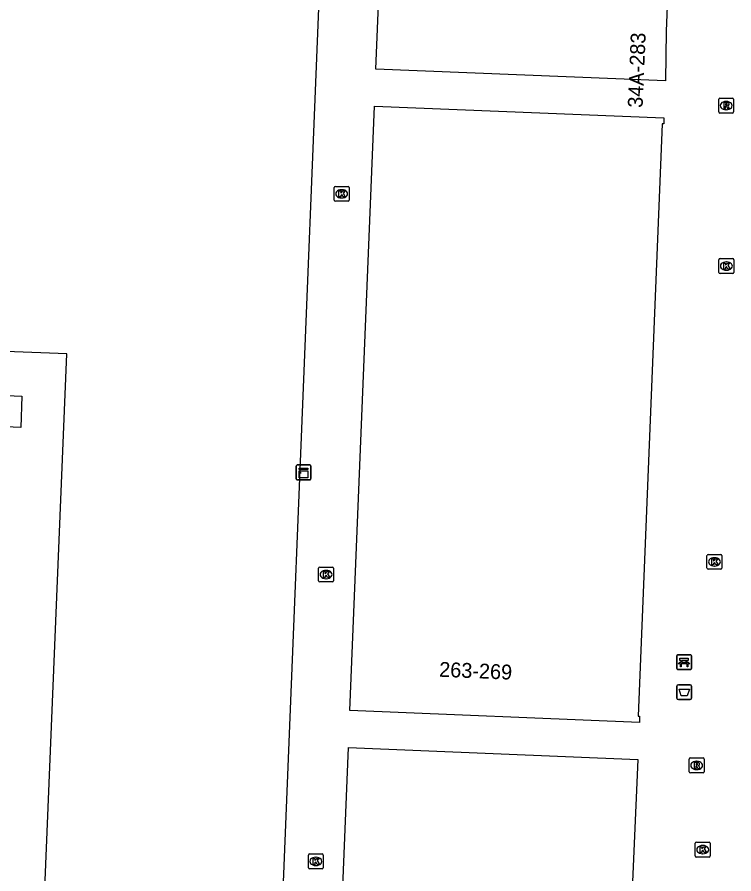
# Model space of a CAD drawing. Extents: x 160891 to 161384, y 386490 to 386907.
# Drawn here: x 161140.9 to 161189.1, y 386595.4 to 386653 of the extents above; entities that cross this region are included whole.
import ezdxf

# ---------------------------------------------------------------- set-up
doc = ezdxf.new("R2010")
doc.units = 0
for name, color, linetype in [('IMGEO_Afvalbak', 7, 'Continuous'), ('IMGEO_Bank', 7, 'Continuous'), ('IMGEO_Kast', 7, 'Continuous'), ('IMGEO_Kolk', 7, 'Continuous'), ('IMGEO_Pand', 7, 'Continuous'), ('IMGEO_Pand_nummerreeks', 7, 'Continuous'), ('IMGEO_Rioolput', 7, 'Continuous'), ('IMGEO_Voetgangersgebied_open', 7, 'Continuous')]:
    doc.layers.add(name, color=color, linetype=linetype)

msp = doc.modelspace()

# ---------------------------------------------------------------- linework, layer by layer
at = {"layer": 'IMGEO_Afvalbak'}
for p, q in [((161185.269, 386607.204), (161185.269, 386608.004)), ((161185.269, 386608.004), (161185.269, 386607.204)), ((161185.369, 386608.104), (161186.159, 386608.104)), ((161186.159, 386608.104), (161185.369, 386608.104)), ((161186.259, 386608.004), (161186.259, 386607.204)), ((161186.259, 386607.204), (161186.259, 386608.004)), ((161186.159, 386607.104), (161185.369, 386607.104)), ((161185.369, 386607.104), (161186.159, 386607.104))]:
    msp.add_line(p, q, dxfattribs=at)
msp.add_lwpolyline([(161185.412, 386607.818), (161186.116, 386607.818), (161185.967, 386607.348), (161185.561, 386607.348), (161185.412, 386607.818)], dxfattribs=at)
for centre, start, end in [((161185.369, 386608.004), 90, 180), ((161185.369, 386608.004), 90, 180), ((161186.159, 386608.004), 0, 90), ((161186.159, 386608.004), 360, 90), ((161185.369, 386607.204), 180, 270), ((161185.369, 386607.204), 180, 270), ((161186.159, 386607.204), 270, 0), ((161186.159, 386607.204), 270, 0)]:
    msp.add_arc(centre, 0.1, start, end, dxfattribs=at)
at = {"layer": 'IMGEO_Bank'}
for p, q in [((161185.256, 386609.198), (161185.256, 386610.039)), ((161185.256, 386610.039), (161185.256, 386609.198)), ((161185.331, 386610.123), (161186.172, 386610.123)), ((161186.172, 386610.123), (161185.331, 386610.123)), ((161186.256, 386610.048), (161186.256, 386609.207)), ((161186.256, 386609.207), (161186.256, 386610.048)), ((161185.953, 386609.521), (161185.56, 386609.521)), ((161185.565, 386609.629), (161185.565, 386609.735)), ((161185.609, 386609.735), (161185.609, 386609.629)), ((161185.897, 386609.741), (161185.615, 386609.741)), ((161185.615, 386609.623), (161185.897, 386609.623)), ((161185.903, 386609.629), (161185.903, 386609.735)), ((161185.947, 386609.735), (161185.947, 386609.629)), ((161186.181, 386609.123), (161185.34, 386609.123)), ((161185.34, 386609.123), (161186.181, 386609.123))]:
    msp.add_line(p, q, dxfattribs=at)
for points in [[(161185.503, 386609.521), (161185.361, 386609.521), (161185.473, 386609.623), (161185.559, 386609.623)], [(161185.559, 386609.741), (161185.473, 386609.741), (161185.473, 386609.902), (161186.036, 386609.902), (161186.036, 386609.741), (161185.953, 386609.741)], [(161185.553, 386609.514), (161185.553, 386609.307), (161185.51, 386609.307), (161185.51, 386609.514)], [(161185.953, 386609.623), (161186.036, 386609.623), (161186.148, 386609.521), (161186.009, 386609.521)], [(161186.003, 386609.514), (161186.003, 386609.307), (161185.959, 386609.307), (161185.959, 386609.514)]]:
    msp.add_lwpolyline(points, dxfattribs=at)
for centre, radius, start, end in [((161185.334, 386610.045), 0.0779, 92.4484, 184.28452), ((161185.334, 386610.045), 0.0779, 92.4484, 184.28452), ((161186.178, 386610.045), 0.0779, 2.4484, 94.28452), ((161186.178, 386610.045), 0.0779, 2.4484, 94.28452), ((161185.503, 386609.514), 0.00671, 2.89567, 87.10433), ((161185.56, 386609.514), 0.00671, 92.89567, 177.10433), ((161185.558, 386609.734), 0.00671, 2.89567, 87.10433), ((161185.558, 386609.63), 0.00671, 272.89567, 357.10433), ((161185.615, 386609.734), 0.00671, 92.89567, 177.10433), ((161185.615, 386609.63), 0.00671, 182.89567, 267.10433), ((161185.897, 386609.734), 0.00671, 2.89567, 87.10433), ((161185.897, 386609.63), 0.00671, 272.89567, 357.10433), ((161185.954, 386609.734), 0.00671, 92.89567, 177.10433), ((161185.954, 386609.63), 0.00671, 182.89567, 267.10433), ((161185.952, 386609.514), 0.00671, 2.89567, 87.10433), ((161186.009, 386609.514), 0.00671, 92.89567, 177.10433), ((161185.334, 386609.201), 0.0779, 182.4484, 274.28452), ((161185.334, 386609.201), 0.0779, 182.4484, 274.28452), ((161186.178, 386609.201), 0.0779, 272.4484, 4.28452), ((161186.178, 386609.201), 0.0779, 272.4484, 4.28452)]:
    msp.add_arc(centre, radius, start, end, dxfattribs=at)
at = {"layer": 'IMGEO_Kast'}
for p, q in [((161159.663, 386621.964), (161159.663, 386622.805)), ((161159.663, 386622.805), (161159.663, 386621.964)), ((161159.738, 386622.889), (161160.579, 386622.889)), ((161160.579, 386622.889), (161159.738, 386622.889)), ((161160.663, 386622.814), (161160.663, 386621.973)), ((161160.663, 386621.973), (161160.663, 386622.814)), ((161160.588, 386621.889), (161159.747, 386621.889)), ((161159.747, 386621.889), (161160.588, 386621.889))]:
    msp.add_line(p, q, dxfattribs=at)
for points in [[(161159.858, 386622.679), (161160.458, 386622.679), (161160.458, 386622.594), (161159.858, 386622.594), (161159.858, 386622.679)], [(161159.858, 386622.504), (161160.458, 386622.504), (161160.458, 386622.015), (161159.858, 386622.015), (161159.858, 386622.504)]]:
    msp.add_lwpolyline(points, dxfattribs=at)
msp.add_circle((161159.942, 386622.353), 0.0377, dxfattribs=at)
for centre, start, end in [((161159.741, 386622.811), 92.4484, 184.28452), ((161159.741, 386622.811), 92.4484, 184.28452), ((161160.585, 386622.811), 2.4484, 94.28452), ((161160.585, 386622.811), 2.4484, 94.28452), ((161159.741, 386621.967), 182.4484, 274.28452), ((161159.741, 386621.967), 182.4484, 274.28452), ((161160.585, 386621.967), 272.4484, 4.28452), ((161160.585, 386621.967), 272.4484, 4.28452)]:
    msp.add_arc(centre, 0.0779, start, end, dxfattribs=at)
at = {"layer": 'IMGEO_Kolk'}
for p, q in [((161162.226, 386640.703), (161162.226, 386641.555)), ((161162.301, 386641.629), (161163.153, 386641.629)), ((161162.714, 386641.409), (161162.739, 386641.409)), ((161163.227, 386641.555), (161163.227, 386640.703)), ((161163.153, 386640.629), (161162.301, 386640.629)), ((161162.737, 386640.849), (161162.712, 386640.849)), ((161188.098, 386635.846), (161188.098, 386636.698)), ((161188.173, 386636.772), (161189.025, 386636.772)), ((161188.586, 386636.552), (161188.611, 386636.552)), ((161189.099, 386636.698), (161189.099, 386635.846)), ((161188.609, 386635.992), (161188.584, 386635.992)), ((161189.025, 386635.772), (161188.173, 386635.772)), ((161187.293, 386615.945), (161187.293, 386616.797)), ((161187.368, 386616.871), (161188.22, 386616.871)), ((161187.781, 386616.651), (161187.806, 386616.651)), ((161188.294, 386616.797), (161188.294, 386615.945)), ((161161.177, 386615.094), (161161.177, 386615.946)), ((161161.252, 386616.02), (161162.104, 386616.02)), ((161161.665, 386615.8), (161161.69, 386615.8)), ((161162.178, 386615.946), (161162.178, 386615.094)), ((161188.22, 386615.871), (161187.368, 386615.871)), ((161187.804, 386616.091), (161187.779, 386616.091)), ((161161.688, 386615.24), (161161.663, 386615.24)), ((161162.104, 386615.02), (161161.252, 386615.02)), ((161186.506, 386596.586), (161186.506, 386597.438)), ((161186.581, 386597.512), (161187.433, 386597.512)), ((161187.507, 386597.438), (161187.507, 386596.586)), ((161186.994, 386597.292), (161187.019, 386597.292)), ((161160.489, 386595.797), (161160.489, 386596.649)), ((161160.564, 386596.723), (161161.416, 386596.723)), ((161160.977, 386596.503), (161161.002, 386596.503)), ((161161.49, 386596.649), (161161.49, 386595.797)), ((161187.433, 386596.512), (161186.581, 386596.512)), ((161187.017, 386596.732), (161186.992, 386596.732)), ((161161.416, 386595.723), (161160.564, 386595.723)), ((161161, 386595.943), (161160.975, 386595.943))]:
    msp.add_line(p, q, dxfattribs=at)
for points in [[(161162.226, 386640.703), (161162.226, 386641.555)], [(161162.301, 386641.629), (161163.153, 386641.629)], [(161162.547, 386641.329), (161162.67, 386641.329), (161162.67, 386641.178), (161162.8, 386641.329), (161162.964, 386641.329), (161162.818, 386641.178), (161162.971, 386640.929), (161162.819, 386640.929), (161162.734, 386641.093), (161162.67, 386641.026), (161162.67, 386640.929), (161162.547, 386640.929), (161162.547, 386641.329)], [(161163.227, 386641.555), (161163.227, 386640.703)], [(161163.153, 386640.629), (161162.301, 386640.629)], [(161188.098, 386635.846), (161188.098, 386636.698)], [(161188.173, 386636.772), (161189.025, 386636.772)], [(161189.099, 386636.698), (161189.099, 386635.846)], [(161188.419, 386636.472), (161188.542, 386636.472), (161188.542, 386636.321), (161188.672, 386636.472), (161188.836, 386636.472), (161188.69, 386636.321), (161188.843, 386636.072), (161188.691, 386636.072), (161188.606, 386636.236), (161188.542, 386636.169), (161188.542, 386636.072), (161188.419, 386636.072), (161188.419, 386636.472)], [(161189.025, 386635.772), (161188.173, 386635.772)], [(161187.293, 386615.945), (161187.293, 386616.797)], [(161187.368, 386616.871), (161188.22, 386616.871)], [(161187.614, 386616.571), (161187.737, 386616.571), (161187.737, 386616.42), (161187.867, 386616.571), (161188.031, 386616.571), (161187.885, 386616.42), (161188.038, 386616.171), (161187.886, 386616.171), (161187.801, 386616.335), (161187.737, 386616.268), (161187.737, 386616.171), (161187.614, 386616.171), (161187.614, 386616.571)], [(161188.294, 386616.797), (161188.294, 386615.945)], [(161161.177, 386615.094), (161161.177, 386615.946)], [(161161.252, 386616.02), (161162.104, 386616.02)], [(161162.178, 386615.946), (161162.178, 386615.094)], [(161188.22, 386615.871), (161187.368, 386615.871)], [(161161.498, 386615.72), (161161.621, 386615.72), (161161.621, 386615.569), (161161.751, 386615.72), (161161.915, 386615.72), (161161.769, 386615.569), (161161.922, 386615.32), (161161.77, 386615.32), (161161.685, 386615.484), (161161.621, 386615.417), (161161.621, 386615.32), (161161.498, 386615.32), (161161.498, 386615.72)], [(161162.104, 386615.02), (161161.252, 386615.02)], [(161186.506, 386596.586), (161186.506, 386597.438)], [(161186.581, 386597.512), (161187.433, 386597.512)], [(161187.507, 386597.438), (161187.507, 386596.586)], [(161186.827, 386597.212), (161186.95, 386597.212), (161186.95, 386597.061), (161187.08, 386597.212), (161187.244, 386597.212), (161187.098, 386597.061), (161187.251, 386596.812), (161187.099, 386596.812), (161187.014, 386596.976), (161186.95, 386596.909), (161186.95, 386596.812), (161186.827, 386596.812), (161186.827, 386597.212)], [(161160.489, 386595.797), (161160.489, 386596.649)], [(161160.564, 386596.723), (161161.416, 386596.723)], [(161160.81, 386596.423), (161160.933, 386596.423), (161160.933, 386596.272), (161161.063, 386596.423), (161161.227, 386596.423), (161161.081, 386596.272), (161161.234, 386596.023), (161161.082, 386596.023), (161160.997, 386596.187), (161160.933, 386596.12), (161160.933, 386596.023), (161160.81, 386596.023), (161160.81, 386596.423)], [(161161.49, 386596.649), (161161.49, 386595.797)], [(161187.433, 386596.512), (161186.581, 386596.512)], [(161161.416, 386595.723), (161160.564, 386595.723)]]:
    msp.add_lwpolyline(points, dxfattribs=at)
for centre, start, end in [((161162.303, 386641.553), 91.55205, 178.44795), ((161162.303, 386641.553), 91.55205, 178.44795), ((161163.151, 386641.553), 1.55205, 88.44795), ((161163.151, 386641.553), 1.55205, 88.44795), ((161162.303, 386640.705), 181.55205, 268.44795), ((161162.303, 386640.705), 181.55205, 268.44795), ((161163.151, 386640.705), 271.55205, 358.44795), ((161163.151, 386640.705), 271.55205, 358.44795), ((161188.175, 386636.696), 91.55205, 178.44795), ((161188.175, 386636.696), 91.55205, 178.44795), ((161189.023, 386636.696), 1.55205, 88.44795), ((161189.023, 386636.696), 1.55205, 88.44795), ((161188.175, 386635.848), 181.55205, 268.44795), ((161188.175, 386635.848), 181.55205, 268.44795), ((161189.023, 386635.848), 271.55205, 358.44795), ((161189.023, 386635.848), 271.55205, 358.44795), ((161187.37, 386616.795), 91.55205, 178.44795), ((161187.37, 386616.795), 91.55205, 178.44795), ((161188.218, 386616.795), 1.55205, 88.44795), ((161188.218, 386616.795), 1.55205, 88.44795), ((161161.254, 386615.944), 91.55205, 178.44795), ((161161.254, 386615.944), 91.55205, 178.44795), ((161162.102, 386615.944), 1.55205, 88.44795), ((161162.102, 386615.944), 1.55205, 88.44795), ((161187.37, 386615.947), 181.55205, 268.44795), ((161187.37, 386615.947), 181.55205, 268.44795), ((161188.218, 386615.947), 271.55205, 358.44795), ((161188.218, 386615.947), 271.55205, 358.44795), ((161161.254, 386615.096), 181.55205, 268.44795), ((161161.254, 386615.096), 181.55205, 268.44795), ((161162.102, 386615.096), 271.55205, 358.44795), ((161162.102, 386615.096), 271.55205, 358.44795), ((161186.583, 386597.436), 91.55205, 178.44795), ((161186.583, 386597.436), 91.55205, 178.44795), ((161187.431, 386597.436), 1.55205, 88.44795), ((161187.431, 386597.436), 1.55205, 88.44795), ((161160.566, 386596.647), 91.55205, 178.44795), ((161160.566, 386596.647), 91.55205, 178.44795), ((161161.414, 386596.647), 1.55205, 88.44795), ((161161.414, 386596.647), 1.55205, 88.44795), ((161186.583, 386596.588), 181.55205, 268.44795), ((161186.583, 386596.588), 181.55205, 268.44795), ((161187.431, 386596.588), 271.55205, 358.44795), ((161187.431, 386596.588), 271.55205, 358.44795), ((161160.566, 386595.799), 181.55205, 268.44795), ((161160.566, 386595.799), 181.55205, 268.44795), ((161161.414, 386595.799), 271.55205, 358.44795), ((161161.414, 386595.799), 271.55205, 358.44795)]:
    msp.add_arc(centre, 0.0765, start, end, dxfattribs=at)
for centre, major_axis, ratio, start_param, end_param in [((161162.713, 386641.129), (-0.387, 0.002), 0.722429, 4.712389, 7.853982), ((161162.738, 386641.129), (-0.39, 0.002), 0.717154, 1.570796, 4.712389), ((161188.585, 386636.272), (-0.387, 0.002), 0.722429, 4.712389, 7.853982), ((161188.61, 386636.272), (-0.39, 0.002), 0.717154, 1.570796, 4.712389), ((161187.78, 386616.371), (-0.387, 0.002), 0.722429, 4.712389, 7.853982), ((161187.805, 386616.371), (-0.39, 0.002), 0.717154, 1.570796, 4.712389), ((161161.664, 386615.52), (-0.387, 0.002), 0.722429, 4.712389, 7.853982), ((161161.689, 386615.52), (-0.39, 0.002), 0.717154, 1.570796, 4.712389), ((161186.993, 386597.012), (-0.387, 0.002), 0.722429, 4.712389, 7.853982), ((161187.018, 386597.012), (-0.39, 0.002), 0.717154, 1.570796, 4.712389), ((161160.976, 386596.223), (-0.387, 0.002), 0.722429, 4.712389, 7.853982), ((161161.001, 386596.223), (-0.39, 0.002), 0.717154, 1.570796, 4.712389)]:
    msp.add_ellipse(centre, major_axis=major_axis, ratio=ratio, start_param=start_param, end_param=end_param, dxfattribs=at)
at = {"layer": 'IMGEO_Pand'}
for points in [[(161143.412, 386571.685), (161142.623, 386572.549), (161142.127, 386573.608), (161141.97, 386574.785), (161144.239, 386630.361), (161136.014, 386630.69), (161138.466, 386692.089), (161139.631, 386693.169), (161152.718, 386692.638), (161152.726, 386692.838), (161153.396, 386709.393)], [(161183.781, 386706.174), (161184.602, 386705.296), (161185.308, 386704.253), (161185.839, 386703.176), (161186.212, 386702.035), (161186.412, 386700.854), (161186.449, 386699.801), (161184.541, 386652.073), (161184.503, 386648.738), (161165.034, 386649.524), (161165.981, 386672.875), (161161.964, 386673.038), (161158.269, 386582.057), (161162.285, 386581.893), (161163.18, 386603.875), (161182.646, 386603.083), (161181.347, 386573.278), (161181.119, 386572.09), (161180.548, 386571.054), (161179.639, 386570.209), (161178.554, 386569.701), (161177.328, 386569.555)], [(161182.662, 386605.991), (161182.762, 386605.989), (161182.75, 386605.57), (161163.276, 386606.37), (161164.933, 386647.036), (161184.399, 386646.246), (161184.381, 386645.831), (161184.281, 386645.835), (161182.662, 386605.991)]]:
    msp.add_lwpolyline(points, dxfattribs=at)
at = {"layer": 'IMGEO_Rioolput'}
for p, q in [((161188.084, 386646.637), (161188.084, 386647.489)), ((161188.159, 386647.563), (161189.011, 386647.563)), ((161189.085, 386647.489), (161189.085, 386646.637)), ((161188.572, 386647.343), (161188.597, 386647.343)), ((161189.011, 386646.563), (161188.159, 386646.563)), ((161188.595, 386646.783), (161188.57, 386646.783)), ((161186.098, 386602.254), (161186.098, 386603.106)), ((161186.173, 386603.18), (161187.025, 386603.18)), ((161187.099, 386603.106), (161187.099, 386602.254)), ((161186.586, 386602.96), (161186.611, 386602.96)), ((161187.025, 386602.18), (161186.173, 386602.18)), ((161186.609, 386602.4), (161186.584, 386602.4))]:
    msp.add_line(p, q, dxfattribs=at)
for points in [[(161188.084, 386646.637), (161188.084, 386647.489)], [(161188.159, 386647.563), (161189.011, 386647.563)], [(161189.085, 386647.489), (161189.085, 386646.637)], [(161188.673, 386647.261), (161188.421, 386647.263), (161188.421, 386646.863)], [(161188.421, 386646.863), (161188.545, 386646.863), (161188.545, 386647.025), (161188.556, 386647.025)], [(161188.599, 386647.182), (161188.545, 386647.182), (161188.545, 386647.101)], [(161188.545, 386647.101), (161188.597, 386647.101)], [(161188.603, 386646.996), (161188.674, 386646.863), (161188.814, 386646.863), (161188.749, 386646.989)], [(161189.011, 386646.563), (161188.159, 386646.563)], [(161186.098, 386602.254), (161186.098, 386603.106)], [(161186.173, 386603.18), (161187.025, 386603.18)], [(161187.099, 386603.106), (161187.099, 386602.254)], [(161186.687, 386602.878), (161186.435, 386602.88), (161186.435, 386602.48)], [(161186.435, 386602.48), (161186.559, 386602.48), (161186.559, 386602.642), (161186.57, 386602.642)], [(161186.613, 386602.799), (161186.559, 386602.799), (161186.559, 386602.718)], [(161186.559, 386602.718), (161186.611, 386602.718)], [(161186.617, 386602.613), (161186.688, 386602.48), (161186.828, 386602.48), (161186.763, 386602.606)], [(161187.025, 386602.18), (161186.173, 386602.18)]]:
    msp.add_lwpolyline(points, dxfattribs=at)
for centre, radius, start, end in [((161188.161, 386647.487), 0.0765, 91.55205, 178.44795), ((161188.161, 386647.487), 0.0765, 91.55205, 178.44795), ((161189.009, 386647.487), 0.0765, 1.55205, 88.44795), ((161189.009, 386647.487), 0.0765, 1.55205, 88.44795), ((161188.555, 386646.972), 0.0533, 26.02933, 88.69889), ((161188.581, 386647.29), 0.19, 274.7715, 282.96867), ((161188.605, 386647.086), 0.0964, 77.00612, 93.18647), ((161188.619, 386647.143), 0.0378, 276.66336, 79.67722), ((161188.672, 386647.151), 0.109, 350.36119, 89.41601), ((161188.67, 386647.151), 0.112, 277.58423, 350.98172), ((161188.654, 386646.936), 0.108, 29.51342, 73.79051), ((161188.161, 386646.639), 0.0765, 181.55205, 268.44795), ((161188.161, 386646.639), 0.0765, 181.55205, 268.44795), ((161189.009, 386646.639), 0.0765, 271.55205, 358.44795), ((161189.009, 386646.639), 0.0765, 271.55205, 358.44795), ((161186.175, 386603.104), 0.0765, 91.55205, 178.44795), ((161186.175, 386603.104), 0.0765, 91.55205, 178.44795), ((161187.023, 386603.104), 0.0765, 1.55205, 88.44795), ((161187.023, 386603.104), 0.0765, 1.55205, 88.44795), ((161186.569, 386602.589), 0.0533, 26.02933, 88.69889), ((161186.595, 386602.907), 0.19, 274.7715, 282.96867), ((161186.619, 386602.703), 0.0964, 77.00612, 93.18647), ((161186.633, 386602.76), 0.0378, 276.66336, 79.67722), ((161186.686, 386602.768), 0.109, 350.36119, 89.41601), ((161186.684, 386602.768), 0.112, 277.58423, 350.98172), ((161186.668, 386602.553), 0.108, 29.51342, 73.79051), ((161186.175, 386602.256), 0.0765, 181.55205, 268.44795), ((161186.175, 386602.256), 0.0765, 181.55205, 268.44795), ((161187.023, 386602.256), 0.0765, 271.55205, 358.44795), ((161187.023, 386602.256), 0.0765, 271.55205, 358.44795)]:
    msp.add_arc(centre, radius, start, end, dxfattribs=at)
for centre, major_axis, ratio, start_param, end_param in [((161188.571, 386647.063), (-0.387, 0.002), 0.722429, 4.712389, 7.853982), ((161188.596, 386647.063), (-0.39, 0.002), 0.717154, 1.570796, 4.712389), ((161186.585, 386602.68), (-0.387, 0.002), 0.722429, 4.712389, 7.853982), ((161186.61, 386602.68), (-0.39, 0.002), 0.717154, 1.570796, 4.712389)]:
    msp.add_ellipse(centre, major_axis=major_axis, ratio=ratio, start_param=start_param, end_param=end_param, dxfattribs=at)
at = {"layer": 'IMGEO_Voetgangersgebied_open'}
msp.add_lwpolyline([(161141.216, 386627.524), (161141.16, 386625.416), (161134.918, 386625.69), (161135.026, 386627.787), (161141.216, 386627.524)], dxfattribs=at)

# ---------------------------------------------------------------- texts
at = {"layer": 'IMGEO_Pand_nummerreeks'}
for s, rotation, p in [('34A-283', 87.55034, (161182.96, 386646.902)), ('263-269', 357.64759, (161169.267, 386608.646))]:
    msp.add_text(s, height=1, rotation=rotation, dxfattribs=at).set_placement(p)

doc.saveas('drawing.dxf')
